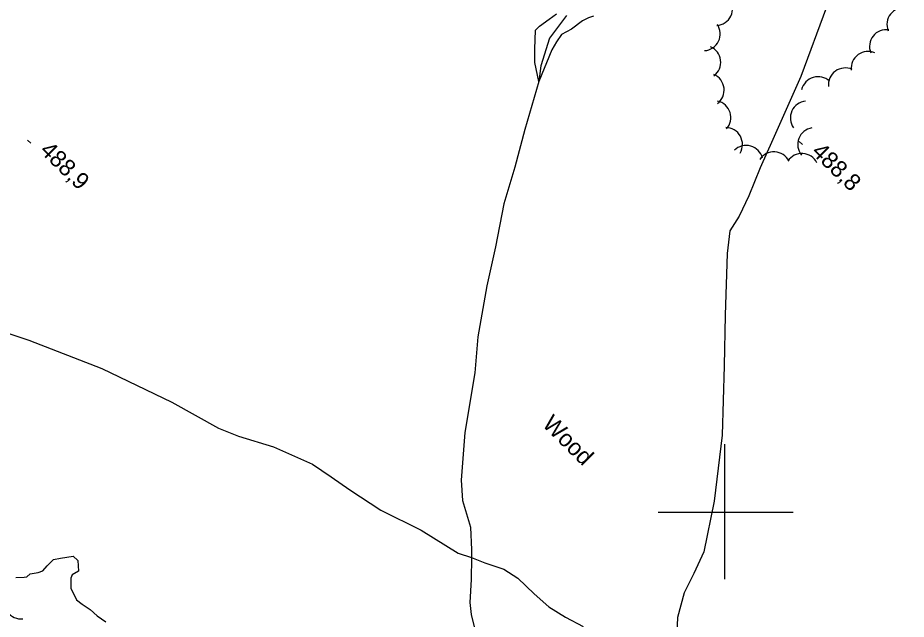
# Model space of a CAD drawing. Extents: x 642515 to 647219, y 6080136 to 6084356.
# Drawn here: x 643274.3 to 643432.3, y 6081981 to 6082088.1 of the extents above; entities that cross this region are included whole.
import ezdxf

# ---------------------------------------------------------------- set-up
doc = ezdxf.new("R2010")
doc.units = 0
for name, color, linetype in [('Level 1', 7, 'Continuous'), ('Level 2', 7, 'Continuous'), ('Level 22', 7, 'Continuous'), ('Level 3', 7, 'Continuous'), ('Level 4', 7, 'Continuous'), ('Level 44', 7, 'Continuous'), ('Level 61', 7, 'Continuous')]:
    doc.layers.add(name, color=color, linetype=linetype)

msp = doc.modelspace()

# ---------------------------------------------------------------- linework, layer by layer
at = {"layer": 'Level 1'}
msp.add_lwpolyline([(643273.96, 6081988.45), (643275.4, 6081988.54), (643275.88, 6081988.57), (643276.49, 6081989.09), (643277.88, 6081989.37), (643278.71, 6081989.62), (643279.5, 6081990.52), (643280.64, 6081991.63), (643281.91, 6081991.87), (643284.14, 6081992.25), (643284.99, 6081991.49), (643285.11, 6081989.56), (643283.94, 6081988.93), (643283.74, 6081988.35), (643283.69, 6081986.58), (643284.7, 6081984.46), (643285.71, 6081983.72), (643287.14, 6081982.75), (643288.42, 6081981.62), (643289.93, 6081980.58)], dxfattribs=at)
at = {"layer": 'Level 2'}
msp.add_lwpolyline([(643376.66, 6082088.32), (643375.79, 6082088.03), (643374.7, 6082087.5), (643372.77, 6082086.04), (643370.97, 6082085.07), (643370.08, 6082083.74), (643369.27, 6082082.35), (643366.97, 6082076.68), (643366.22, 6082080.07), (643366.25, 6082082.46), (643366.38, 6082085.82), (643367.07, 6082086.57), (643368.77, 6082087.78), (643370.09, 6082088.73)], dxfattribs=at)
at = {"layer": 'Level 22'}
for points in [[(643418.14, 6082089.92), (643413.53, 6082077.58), (643408.58, 6082066.4), (643406.33, 6082061.33), (643404.28, 6082056.38), (643402.56, 6082052.75), (643400.93, 6082050.16), (643400.44, 6082046.11), (643400.12, 6082035.13), (643399.92, 6082026.1), (643399.55, 6082013.79), (643398.15, 6082002.04), (643396.29, 6081993.05), (643394.51, 6081989.17), (643392.77, 6081985.7), (643391.62, 6081981.34), (643391.39, 6081976.01)], [(643269.34, 6082032.99), (643276.25, 6082030.67), (643289.21, 6082025.65), (643301.7, 6082019.68), (643309.96, 6082015.03), (643313.55, 6082013.59), (643319.79, 6082011.71), (643326.71, 6082008.63), (643330.03, 6082006.37), (643333.36, 6082004.04), (643338.86, 6082000.46), (643346.01, 6081996.86), (643352.59, 6081992.79), (643354.97, 6081991.99), (643357.33, 6081991.05), (643360.7, 6081989.96), (643363.21, 6081988.34), (643366.13, 6081985.54), (643368.72, 6081983.24), (643371.7, 6081981.37), (643374.82, 6081979.74)]]:
    msp.add_lwpolyline(points, dxfattribs=at)
at = {"layer": 'Level 3'}
for p, q in [((643276.02, 6082066.28), (643276.59, 6082065.72)), ((643413.26, 6082066.04), (643413.83, 6082065.48))]:
    msp.add_line(p, q, dxfattribs=at)
at = {"layer": 'Level 4'}
msp.add_lwpolyline([(643371.86, 6082088.48), (643368.82, 6082084.41), (643367.33, 6082079.49), (643366.97, 6082076.68), (643364.49, 6082068.16), (643362.66, 6082061.49), (643360.74, 6082054.97), (643359.25, 6082047.31), (643357.72, 6082040.37), (643356.11, 6082031.3), (643355.57, 6082024.86), (643353.82, 6082014.25), (643353.13, 6082005.76), (643353.35, 6082002.15), (643354.81, 6081997.44), (643354.98, 6081993.35), (643354.97, 6081991.99), (643354.94, 6081988.07), (643354.67, 6081983.99), (643354.92, 6081981.87), (643355.46, 6081979.65)], dxfattribs=at)
at = {"layer": 'Level 44'}
for centre, start, end in [((643398.42, 6082089.68), 273.7961, 33.7741), ((643431.86, 6082086.86), 81.7122, 201.6901), ((643396.21, 6082085.19), 273.7961, 33.7741), ((643428.76, 6082082.93), 81.7122, 201.6901), ((643396.3, 6082080.14), 306.9641, 66.9421), ((643425.5, 6082079.06), 65.9976, 185.9756), ((643421.45, 6082076.12), 65.9976, 185.9756), ((643396.91, 6082075.18), 306.9641, 66.9421), ((643416.61, 6082074.57), 46.8454, 166.8233), ((643398.11, 6082070.29), 317.7474, 77.7254), ((643414.68, 6082070.22), 95.3251, 215.303), ((643400.17, 6082065.51), 329.1911, 89.1691), ((643415.99, 6082065.5), 99.0496, 219.0276), ((643403.83, 6082062.33), 14.5372, 134.5151), ((643408.74, 6082061.2), 26.5641, 146.5421), ((643413.73, 6082060.9), 26.5641, 146.5421), ((643274.9, 6081984.08), 155.7629, 275.7408)]:
    msp.add_arc(centre, 3, start, end, dxfattribs=at)
at = {"layer": 'Level 61'}
for p, q in [((643400, 6082012.16), (643400, 6081988.16)), ((643412.16, 6082000), (643388.16, 6082000))]:
    msp.add_line(p, q, dxfattribs=at)

# ---------------------------------------------------------------- texts
at = {"layer": 'Level 3'}
for s, p in [('488,9', (643278.05, 6082064.23)), ('488,8', (643415.29, 6082064))]:
    msp.add_text(s, height=3, rotation=315.59, dxfattribs=at).set_placement(p)
at = {"layer": 'Level 44'}
msp.add_text('Wood', height=3, rotation=315.1749, dxfattribs=at).set_placement((643367.4, 6082015.55))

doc.saveas('drawing.dxf')
